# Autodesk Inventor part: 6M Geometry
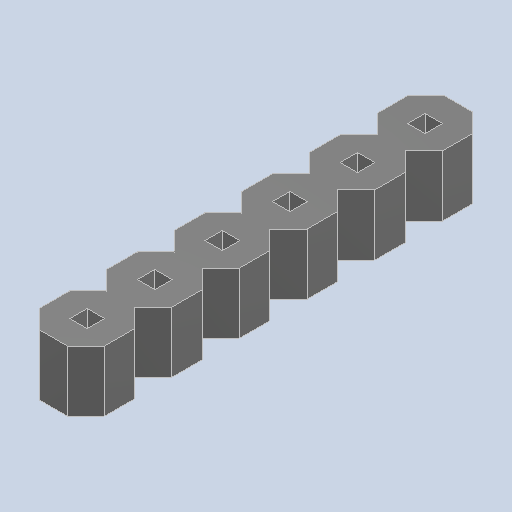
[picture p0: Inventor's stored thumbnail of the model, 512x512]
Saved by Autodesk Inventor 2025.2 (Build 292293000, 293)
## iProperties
Created: 2025-04
Part Number: 6M Geometry
Material: Generic
Description: PART-6M Geometry-DESC
Document SubType Name: Modeling
Designer: BennF
Density: 1 g/cm^3
Appearance: Default
Author: BennF
Revision Number: NONE
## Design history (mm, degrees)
feature "6"
body "Solid1"
